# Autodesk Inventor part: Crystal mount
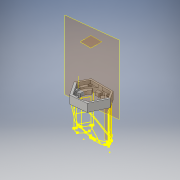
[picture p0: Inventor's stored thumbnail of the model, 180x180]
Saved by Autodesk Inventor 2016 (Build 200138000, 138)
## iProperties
Created: 2015-09
Part Number: Crystal mount
Material: Generic
Document SubType Name: Modeling
Designer: Z
Density: 1 g/cm^3
Appearance: Default
Author: Z
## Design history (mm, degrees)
derived "cane mount.ipt"
  sketch "Sketch37"
    geometry: L1 (7.76, 0)-(8.043, 0) reference; L2 (19.064, 57.15)-(19.064, 0) reference; L3 (15.314, 0)-(15.314, 50.8) reference; L4 (15.314, 50.8)-(8.043, 50.8) reference; L5 (8.043, 0)-(8.043, 50.8) reference; L6 (8.043, 57.15)-(19.064, 57.15) reference; L7 (8.043, 50.8)-(8.043, 57.15) reference; L8 (0, 50.8)-(0, 0) reference; L9 (7.76, 50.8)-(7.76, 0) reference; L10 (7.76, 50.8)-(0, 50.8) reference; L11 (-3.767, 0)-(-3.767, 63.5) reference; L12 (-3.767, 63.5)-(7.76, 63.5) reference; L13 (7.76, 63.5)-(7.76, 50.8) reference; L14 (15.314, 3.175)-(0, 3.175) reference; L15 (0, 3.175)-(0, 15.875) reference; L16 (0, 15.875)-(15.314, 15.875) reference; L17 (15.314, 15.875)-(15.314, 3.175) reference; 5 further points
  sketch "Sketch38"
    geometry: L1 (-12.361, 64.822)-(-4.847, 64.822) reference; L2 (-4.847, 64.822)-(7.871, 9.897) reference; L3 (7.871, 9.897)-(5.044, 0.782) reference; L4 (-56.252, 0.782)-(-58.671, 11.761) reference; L5 (-58.671, 11.761)-(-43.805, 64.822) reference; L6 (-43.805, 64.822)-(-37.173, 64.822) reference; L7 (-40.964, 57.706)-(-42.061, 57.706) reference; L8 (-42.061, 57.706)-(-55.048, 11.353) reference; L9 (-55.048, 11.353)-(-52.719, 0.782) reference; L10 (1.192, 0.782)-(4.181, 10.421) reference; L11 (4.181, 10.421)-(-6.768, 57.706) reference; L12 (-6.768, 57.706)-(-8.569, 57.706) reference; L13 (-24.767, 23.835)-(-24.767, -28.939) reference; C1 r 1.5 at (-24.767, -22.589) reference; 14 further points; 3 other entities
    constraints: 3 other
  sketch "Sketch39"
    geometry: L1 (-25.388, 57.15)-(-14.362, 57.15) reference; L2 (-14.362, 57.15)-(-14.362, 50.8) reference; L3 (-14.362, 50.8)-(-14.362, 0) reference; L4 (-14.362, 0)-(-14.4, 0) reference; L5 (-21.781, 50.8)-(-21.781, 0) reference; L6 (-14.362, 50.8)-(-21.781, 50.8) reference; L7 (-25.388, 0.007)-(-25.388, 57.15) reference; L8 (-14.4, 0)-(-7.597, -10.524) reference; L9 (-7.597, -10.524)-(-14.054, 0) reference; L10 (0, 50.8)-(-14.054, 50.8) reference; L11 (-14.054, 0)-(-14.054, 50.8) reference; L12 (-14.054, 50.8)-(-14.054, 63.5) reference; L13 (-14.054, 63.5)-(3.595, 63.5) reference; L14 (3.595, 63.5)-(3.595, 0.004) reference; L15 (0, 0)-(0, 50.8) reference; L16 (-21.781, 25.4)-(0, 25.4) reference; L17 (0, 25.4)-(0, 6.35) reference; L18 (0, 6.35)-(-21.781, 6.35) reference; L19 (-21.781, 6.35)-(-21.781, 25.4) reference; 3 further points
feature "Solid3::cane mount.ipt" dims "d0" = 10
tag "TaggingFeature1"
workplane "Work Plane6"
workplane "Work Plane7"
workplane "Work Plane14"
workaxis "Work Axis2"
body "Solid1"
